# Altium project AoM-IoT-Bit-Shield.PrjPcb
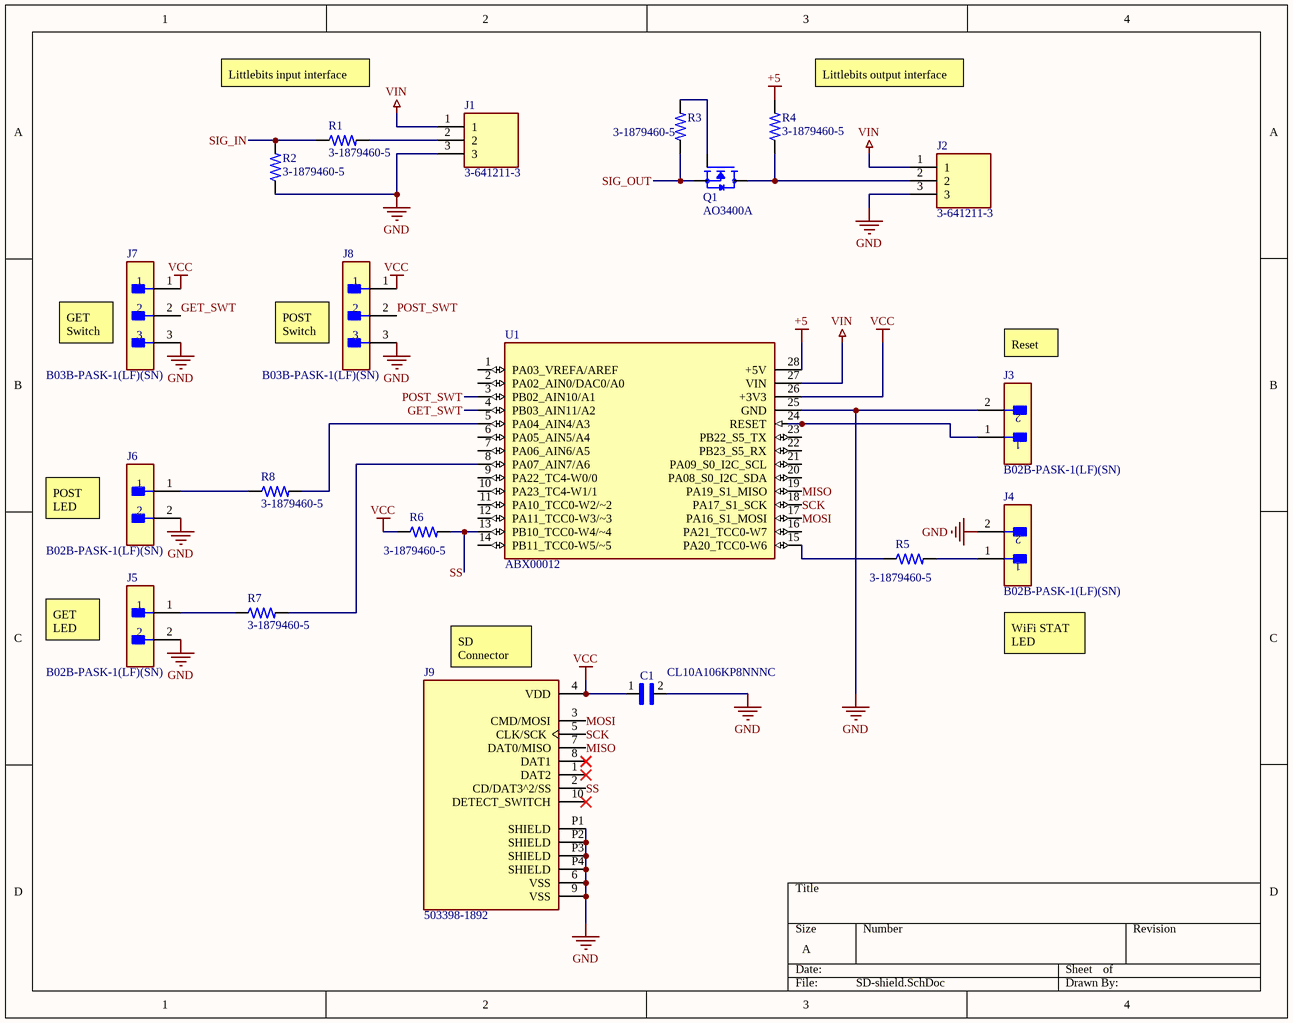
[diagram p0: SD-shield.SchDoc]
1 sheet, 20 parts. Net scope: global (net labels, ports and power ports of the same name join across sheets).
Board file: AoM-IoT-Bit-Shield-v1.0.PcbDoc

## Sheet SD-shield.SchDoc
size A; SheetNumber: 1; SheetTotal: 1

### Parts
C1  CL10A106KP8NNNC  [CAPC1608X90N]
J1  3-641211-3  [TE_3-641211-3]
J2  3-641211-3  [TE_3-641211-3]
J3  B02B-PASK-1(LF)(SN)  [FP-B02B-PASK-1_LF_SN-MFG]
J4  B02B-PASK-1(LF)(SN)  [FP-B02B-PASK-1_LF_SN-MFG]
J5  B02B-PASK-1(LF)(SN)  [FP-B02B-PASK-1_LF_SN-MFG]
J6  B02B-PASK-1(LF)(SN)  [FP-B02B-PASK-1_LF_SN-MFG]
J7  B03B-PASK-1(LF)(SN)  [FP-B03B-PASK-1_LF_SN-MFG]
J8  B03B-PASK-1(LF)(SN)  [FP-B03B-PASK-1_LF_SN-MFG]
J9  503398-1892  [MOLEX_503398-1892]
Q1  AO3400A  [SOT95P280X125-3N]
R1  3-1879460-5  [RESC1608X50N]
R2  3-1879460-5  [RESC1608X50N]
R3  3-1879460-5  [RESC1608X50N]
R4  3-1879460-5  [RESC1608X50N]
R5  3-1879460-5  [RESC1608X50N]
R6  3-1879460-5  [RESC1608X50N]
R7  3-1879460-5  [RESC1608X50N]
R8  3-1879460-5  [RESC1608X50N]
U1  ABX00012  [ARDUINO_ABX00012]

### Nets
+5: R4.2 U1.28(+5V)
GND: C1.2 J1.3 J2.3 J3.2 J4.2 J5.2 J6.2 J7.3 J8.3 J9.6(VSS) J9.9(VSS) J9.P1(SHIELD) J9.P2(SHIELD) J9.P3(SHIELD) J9.P4(SHIELD) R2.1 U1.25(GND)
VCC: C1.1 J7.1 J8.1 J9.4(VDD) R6.1 U1.26(+3V3)
VIN: J1.1 J2.1 U1.27(VIN)
GET_SWT: J7.2 U1.4(PB03_AIN11/A2)
MISO: J9.7(DAT0/MISO) U1.19(PA19_S1_MISO)
MOSI: J9.3(CMD/MOSI) U1.17(PA16_S1_MOSI)
POST_SWT: J8.2 U1.3(PB02_AIN10/A1)
SCK: J9.5(CLK/SCK) U1.18(PA17_S1_SCK)
SIG_IN: R1.1 R2.2
SIG_OUT: Q1.2(S) R3.1
SS: J9.2(CD/DAT3^2/SS) R6.2 U1.13(PB10_TCC0-W4/~4)
NetJ1_2: J1.2 R1.2
NetJ2_2: J2.2 Q1.3(D) R4.1
NetJ3_1: J3.1 U1.24(RESET)
NetJ4_1: J4.1 R5.2
NetJ5_1: J5.1 R7.1
NetJ6_1: J6.1 R8.1
NetQ1_1: Q1.1(G) R3.2
NetR5_1: R5.1 U1.15(PA20_TCC0-W6)
NetR7_2: R7.2 U1.8(PA07_AIN7/A6)
NetR8_2: R8.2 U1.5(PA04_AIN4/A3)

Not connected (* = marked no-connect by the designer): J9 1(DAT2)* 8(DAT1)* 10(DETECT_SWITCH)*; U1 1(PA03_VREFA/AREF) 2(PA02_AIN0/DAC0/A0) 6(PA05_AIN5/A4) 7(PA06_AIN6/A5) 9(PA22_TC4-W0/0) 10(PA23_TC4-W1/1) 11(PA10_TCC0-W2/~2) 12(PA11_TCC0-W3/~3) 14(PB11_TCC0-W5/~5) 16(PA21_TCC0-W7) 20(PA08_S0_I2C_SDA) 21(PA09_S0_I2C_SCL) 22(PB23_S5_RX) 23(PB22_S5_TX)

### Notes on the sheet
- Littlebits input interface
- (near R4) Littlebits output interface
- (near J7) GET Switch
- (near J8) POST Switch
- Reset
- POST LED
- GET LED
- (near J9) SD Connector
- WiFi STAT LED

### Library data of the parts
C1 = CL10A106KP8NNNC: 10ÂµF Â±10% 10V Ceramic Capacitor X5R 0603 _1608 Metric_; MF: Samsung
J3-J6 = CMP-17439-000415-1: CONN HEADER VERT 2POS 2MM; Number of Contacts: 2; Current Rating: 3A; Insulation Resistance: 1GR; Mated Stacking Heights: 14.9mm; Voltage Rating: 250V; Gender: Male
J7 J8 = CMP-17439-000193-1: CONN HEADER VERT 3POS 2MM; Voltage Rating: 250V; Current Rating: 3A; Mated Stacking Heights: 14.9mm; Number of Positions: 3
J9 = 503398-1892: 9 (8 + 1) Position Card Connector Secure Digital - microSDâ„¢ Surface Mount, Right Angle Gold; MP: 5033981892; MF: Molex
Q1 = AO3400A: Trans MOSFET N-CH 30V 5.7A 3-Pin SOT-23
R1-R8 = 3-1879460-5: RES 0.27 OHM 1% 1/10W 0603; Resistance: 27; MF: TE Connectivity; Power_Rating: .1 W
U1 = ABX00012: MKR footprint/pins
